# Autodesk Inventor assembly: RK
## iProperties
Company: Scholle und Partner GmbH
Shininess: 64.0
Length Units: 11269
Angle Units: 11279
Time Units: 11290
Mass Units: 11283
Length Display Precision: 3
Angle Display Precision: 2
Compacted: True
Created: 2004-10
Part Number: RK
Document SubType Name: Assembly
Designer: mp
Density: 0.0
Volumn: 0.0
Area: 0.0
PropertySet Name: Model Information
Control State: 0
Master: False
Checked Out: False
Author: Michael Puschner
Comments: www.scholle.de
